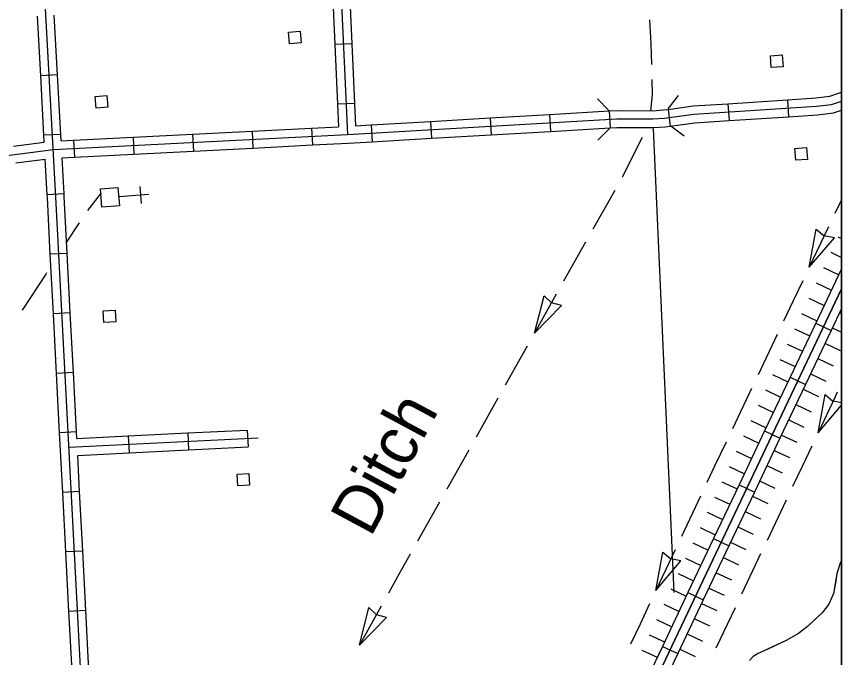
# Model space of a CAD drawing. Extents: x -0.3 to 2.65, y 0 to 1.9.
# Drawn here: x 0.9445 to 1.0319, y 0.2492 to 0.3171 of the extents above; entities that cross this region are included whole.
import ezdxf

# ---------------------------------------------------------------- set-up
doc = ezdxf.new("R2010")
doc.units = 0
for name, color, linetype in [('DSN_DRFT_DNC', 7, 'Continuous'), ('Level 12', 7, 'Continuous'), ('Level 15', 7, 'Continuous'), ('Level 19', 7, 'Continuous'), ('Level 20', 7, 'Continuous'), ('Level 29', 7, 'Continuous'), ('Level 32', 7, 'Continuous'), ('Level 33', 7, 'Continuous'), ('Level 36', 7, 'Continuous'), ('Level 37', 7, 'Continuous'), ('Level 6', 7, 'Continuous')]:
    doc.layers.add(name, color=color, linetype=linetype)

msp = doc.modelspace()

# ---------------------------------------------------------------- linework, layer by layer
at = {"layer": 'DSN_DRFT_DNC'}
msp.add_lwpolyline([(0.38477, 0.541667), (1.031896, 0.541667), (1.031896, 0.144296), (0.38477, 0.144296)], close=True, dxfattribs=at)
at = {"layer": 'Level 12'}
for p, q in [((1.031886, 0.297696), (1.031195, 0.296244)), ((1.028481, 0.290539), (1.029225, 0.294577)), ((1.029225, 0.294577), (1.030057, 0.293868)), ((1.031145, 0.293664), (1.03007, 0.293862)), ((1.028481, 0.290539), (1.031145, 0.293664)), ((0.99935, 0.283548), (1.000367, 0.287527)), ((1.000367, 0.287527), (1.001149, 0.286763)), ((0.99935, 0.283548), (1.00222, 0.286485)), ((1.00222, 0.286485), (1.001161, 0.286756)), ((1.029418, 0.273004), (1.030158, 0.277044)), ((1.030158, 0.277044), (1.030991, 0.276335)), ((1.031886, 0.276168), (1.031004, 0.276329)), ((1.029418, 0.273004), (1.031886, 0.275906)), ((1.012229, 0.25629), (1.012963, 0.260331)), ((1.012963, 0.260331), (1.013797, 0.259624)), ((1.012229, 0.25629), (1.014885, 0.259423)), ((1.014885, 0.259423), (1.01381, 0.259618)), ((0.980824, 0.250474), (0.981816, 0.254459)), ((0.981816, 0.254459), (0.982603, 0.2537)), ((0.983676, 0.253429), (0.982615, 0.253693)), ((0.980824, 0.250474), (0.983676, 0.253429))]:
    msp.add_line(p, q, dxfattribs=at)
for points in [[(1.011564, 0.316751), (1.011693, 0.314214), (1.011751, 0.312017)], [(1.011792, 0.310438), (1.011834, 0.30884), (1.011664, 0.307139)], [(1.010765, 0.304304), (1.010633, 0.304062), (1.008712, 0.300208), (1.008636, 0.300071)], [(0.95344, 0.298424), (0.951995, 0.296546)], [(1.007862, 0.298694), (1.00554, 0.294563)], [(0.951087, 0.295256), (0.949735, 0.293179)], [(1.030516, 0.294818), (1.028481, 0.290539)], [(1.004767, 0.293187), (1.002445, 0.289056)], [(0.94764, 0.28996), (0.94755, 0.289822), (0.945041, 0.285998)], [(1.027802, 0.289112), (1.026784, 0.286973)], [(1.001671, 0.287679), (0.99935, 0.283548)], [(1.026784, 0.286973), (1.025766, 0.284833)], [(1.025088, 0.283407), (1.023052, 0.279128)], [(0.998576, 0.282171), (0.996254, 0.27804)], [(1.022373, 0.277702), (1.020338, 0.273423)], [(1.031451, 0.277284), (1.031219, 0.276801), (1.029418, 0.273004)], [(0.99548, 0.276663), (0.993159, 0.272532)], [(1.019659, 0.271996), (1.018447, 0.26945), (1.018445, 0.269445), (1.017628, 0.267715)], [(0.992385, 0.271155), (0.990063, 0.267024)], [(1.028741, 0.271577), (1.027726, 0.269436)], [(1.027726, 0.269436), (1.02671, 0.267295)], [(1.016953, 0.266287), (1.014928, 0.262003)], [(1.026033, 0.265868), (1.024003, 0.261587)], [(0.989289, 0.265647), (0.986968, 0.261516)], [(1.014254, 0.260574), (1.012229, 0.25629)], [(0.986194, 0.260139), (0.985064, 0.258129), (0.983885, 0.256001)], [(1.023326, 0.26016), (1.021295, 0.255878)], [(0.98312, 0.254619), (0.980823, 0.250474)], [(1.011554, 0.254862), (1.010542, 0.25272)], [(1.020618, 0.254451), (1.018587, 0.25017)], [(1.010542, 0.25272), (1.00953, 0.250578)]]:
    msp.add_lwpolyline(points, dxfattribs=at)
at = {"layer": 'Level 15'}
for p, q in [((0.979991, 0.31422), (0.978198, 0.314138)), ((0.948812, 0.310937), (0.94702, 0.310838)), ((0.980278, 0.307908), (0.978485, 0.307827)), ((1.019861, 0.307881), (1.019978, 0.30609)), ((1.026166, 0.308293), (1.026283, 0.306502)), ((1.007271, 0.307108), (1.007376, 0.305316)), ((1.013514, 0.30728), (1.013755, 0.305501)), ((0.994657, 0.30637), (0.994761, 0.304578)), ((1.000964, 0.306739), (1.001069, 0.304947)), ((0.97574, 0.305292), (0.975831, 0.3035)), ((0.982042, 0.305632), (0.982147, 0.30384)), ((0.988349, 0.306001), (0.988454, 0.304209)), ((0.949157, 0.304628), (0.947365, 0.30453)), ((0.95681, 0.30433), (0.956901, 0.302537)), ((0.96312, 0.304651), (0.963211, 0.302858)), ((0.96943, 0.304971), (0.969521, 0.303179)), ((0.9505, 0.304009), (0.950591, 0.302216)), ((0.949503, 0.298319), (0.94771, 0.298221)), ((0.949832, 0.292007), (0.94804, 0.291914)), ((1.031886, 0.290341), (1.031874, 0.290316)), ((1.031874, 0.290316), (1.031886, 0.29031)), ((1.031886, 0.286153), (1.030787, 0.283838)), ((0.950161, 0.285698), (0.948369, 0.285604)), ((1.029166, 0.284607), (1.030787, 0.283838)), ((0.95049, 0.279388), (0.948698, 0.279295)), ((1.026458, 0.278899), (1.028079, 0.27813)), ((0.950819, 0.273079), (0.949027, 0.272985)), ((0.962609, 0.272972), (0.962698, 0.271179)), ((0.96892, 0.273285), (0.969009, 0.271492)), ((1.023749, 0.273191), (1.025371, 0.272421)), ((0.956299, 0.272658), (0.956388, 0.270866)), ((0.951148, 0.266769), (0.949356, 0.266676)), ((1.021041, 0.267482), (1.022663, 0.266713)), ((1.018333, 0.261774), (1.019955, 0.261005)), ((0.951477, 0.260459), (0.949685, 0.260366)), ((1.015625, 0.256066), (1.017247, 0.255296)), ((0.951806, 0.25415), (0.950013, 0.254056)), ((1.012917, 0.250357), (1.014539, 0.249588))]:
    msp.add_line(p, q, dxfattribs=at)
for points in [[(0.980914, 0.375083), (0.977798, 0.372691), (0.976942, 0.371974), (0.976392, 0.371185), (0.976158, 0.370335), (0.975971, 0.369189), (0.976279, 0.368153), (0.976461, 0.365336), (0.977251, 0.346933), (0.977728, 0.340622), (0.978318, 0.33161), (0.979546, 0.304604)], [(0.948639, 0.297983), (0.944541, 0.372833)], [(0.977911, 0.32045), (0.978198, 0.314138)], [(0.979704, 0.320532), (0.979991, 0.31422)], [(0.94702, 0.310838), (0.946674, 0.317147)], [(0.948812, 0.310937), (0.948466, 0.317245)], [(0.978198, 0.314138), (0.978485, 0.307827)], [(0.979991, 0.31422), (0.980278, 0.307908)], [(0.947365, 0.30453), (0.94702, 0.310838)], [(0.949157, 0.304628), (0.948812, 0.310937)], [(1.026166, 0.308293), (1.029168, 0.30849), (1.030651, 0.308672), (1.031697, 0.309012), (1.031886, 0.309096)], [(0.948349, 0.303017), (0.979546, 0.304604), (1.008074, 0.306273), (1.011914, 0.306257), (1.013131, 0.306339), (1.016253, 0.306762), (1.02925, 0.307613), (1.030842, 0.307808), (1.031886, 0.308147)], [(0.978485, 0.307827), (0.978594, 0.305437)], [(0.980278, 0.307908), (0.980386, 0.305535)], [(1.013514, 0.30728), (1.016165, 0.307639), (1.019861, 0.307881)], [(1.019861, 0.307881), (1.026166, 0.308293)], [(1.000964, 0.306739), (1.007271, 0.307108)], [(1.007271, 0.307108), (1.00805, 0.307154), (1.011886, 0.307138), (1.013042, 0.307216), (1.013514, 0.30728)], [(1.026283, 0.306502), (1.029336, 0.306702), (1.031041, 0.306912), (1.031886, 0.307186)], [(0.988349, 0.306001), (0.994657, 0.30637)], [(0.994657, 0.30637), (1.000964, 0.306739)], [(1.013755, 0.305501), (1.016344, 0.305852), (1.019978, 0.30609)], [(1.019978, 0.30609), (1.026283, 0.306502)], [(0.96943, 0.304971), (0.97574, 0.305292)], [(0.97574, 0.305292), (0.978594, 0.305437)], [(0.980386, 0.305535), (0.982042, 0.305632)], [(0.982042, 0.305632), (0.988349, 0.306001)], [(1.001069, 0.304947), (1.007376, 0.305316)], [(1.007376, 0.305316), (1.008099, 0.305358), (1.011943, 0.305343), (1.013223, 0.305429), (1.013755, 0.305501)], [(0.947406, 0.303786), (0.947365, 0.30453)], [(0.949195, 0.303942), (0.949157, 0.304628)], [(0.9505, 0.304009), (0.95681, 0.30433)], [(0.95681, 0.30433), (0.96312, 0.304651)], [(0.96312, 0.304651), (0.96943, 0.304971)], [(0.988454, 0.304209), (0.994761, 0.304578)], [(0.994761, 0.304578), (1.001069, 0.304947)], [(0.944151, 0.303377), (0.947406, 0.303786)], [(0.949195, 0.303942), (0.9505, 0.304009)], [(0.969521, 0.303179), (0.975831, 0.3035)], [(0.975831, 0.3035), (0.979596, 0.303691), (0.982147, 0.30384)], [(0.982147, 0.30384), (0.988454, 0.304209)], [(0.82448, 0.29532), (0.861174, 0.296964), (0.869268, 0.297214), (0.882271, 0.297741), (0.885311, 0.298019), (0.890649, 0.298892), (0.9031, 0.299971), (0.907709, 0.300247), (0.912716, 0.300468), (0.926784, 0.301246), (0.939403, 0.302056), (0.943185, 0.302368), (0.948349, 0.303017)], [(0.950591, 0.302216), (0.956901, 0.302537)], [(0.956901, 0.302537), (0.963211, 0.302858)], [(0.963211, 0.302858), (0.969521, 0.303179)], [(0.944375, 0.301596), (0.947504, 0.30199)], [(0.94771, 0.298221), (0.947504, 0.30199)], [(0.949293, 0.30215), (0.950591, 0.302216)], [(0.949503, 0.298319), (0.949293, 0.30215)], [(0.94804, 0.291914), (0.947726, 0.297934), (0.94771, 0.298221)], [(0.949832, 0.292007), (0.949518, 0.29803), (0.949503, 0.298319)], [(0.952994, 0.176198), (0.954135, 0.176338), (0.954452, 0.176453), (0.954691, 0.176672), (0.954797, 0.176907), (0.954759, 0.178156), (0.953909, 0.199316), (0.953966, 0.199969), (0.954188, 0.200668), (0.954642, 0.201513), (0.954847, 0.202103), (0.95484, 0.202415), (0.954669, 0.202682), (0.953465, 0.203597), (0.953164, 0.204036), (0.953059, 0.2048), (0.953132, 0.205394), (0.953481, 0.206991), (0.953507, 0.207774), (0.951694, 0.239369), (0.948639, 0.297983)], [(0.948369, 0.285604), (0.94804, 0.291914)], [(0.950161, 0.285698), (0.949832, 0.292007)], [(1.031874, 0.290316), (1.029166, 0.284607)], [(0.948698, 0.279295), (0.948369, 0.285604)], [(0.95049, 0.279388), (0.950161, 0.285698)], [(1.029166, 0.284607), (1.026458, 0.278899)], [(1.030787, 0.283838), (1.028079, 0.27813)], [(0.949027, 0.272985), (0.948698, 0.279295)], [(0.950819, 0.273079), (0.95049, 0.279388)], [(1.026458, 0.278899), (1.023749, 0.273191)], [(1.028079, 0.27813), (1.025371, 0.272421)], [(0.949356, 0.266676), (0.949027, 0.272985)], [(0.950855, 0.272388), (0.950819, 0.273079)], [(0.956299, 0.272658), (0.962609, 0.272972)], [(0.962609, 0.272972), (0.96892, 0.273285)], [(1.023749, 0.273191), (1.021041, 0.267482)], [(0.950032, 0.271465), (0.970086, 0.272461)], [(0.950855, 0.272388), (0.956299, 0.272658)], [(1.025371, 0.272421), (1.022663, 0.266713)], [(0.956388, 0.270866), (0.962698, 0.271179)], [(0.962698, 0.271179), (0.969009, 0.271492)], [(0.950949, 0.270595), (0.956388, 0.270866)], [(0.951148, 0.266769), (0.950949, 0.270595)], [(0.951477, 0.260459), (0.951148, 0.266769)], [(1.021041, 0.267482), (1.018333, 0.261774)], [(1.022663, 0.266713), (1.019955, 0.261005)], [(0.949685, 0.260366), (0.949356, 0.266676)], [(1.018333, 0.261774), (1.015625, 0.256066)], [(1.019955, 0.261005), (1.017247, 0.255296)], [(0.950013, 0.254056), (0.949685, 0.260366)], [(0.951806, 0.25415), (0.951477, 0.260459)], [(1.015625, 0.256066), (1.012917, 0.250357)], [(1.017247, 0.255296), (1.014539, 0.249588)], [(0.950342, 0.247747), (0.950013, 0.254056)], [(0.952135, 0.24784), (0.951806, 0.25415)], [(1.012917, 0.250357), (1.010209, 0.244649)], [(1.014539, 0.249588), (1.011831, 0.243879)]]:
    msp.add_lwpolyline(points, dxfattribs=at)
at = {"layer": 'Level 19'}
for points in [[(0.973379, 0.314235), (0.973283, 0.315477), (0.974528, 0.315573), (0.974625, 0.314331)], [(1.024454, 0.311701), (1.024358, 0.312943), (1.025604, 0.31304), (1.0257, 0.311798)], [(0.952889, 0.307404), (0.952792, 0.308646), (0.954038, 0.308743), (0.954134, 0.307501)], [(1.027053, 0.301883), (1.026957, 0.303125), (1.028202, 0.303221), (1.028298, 0.301979)], [(0.953725, 0.284692), (0.953651, 0.285935), (0.954898, 0.286009), (0.954972, 0.284766)], [(0.967904, 0.267361), (0.96783, 0.268604), (0.969077, 0.268678), (0.969151, 0.267435)]]:
    msp.add_lwpolyline(points, close=True, dxfattribs=at)
at = {"layer": 'Level 20'}
msp.add_lwpolyline([(1.011933, 0.305258), (1.014134, 0.256058)], dxfattribs=at)
at = {"layer": 'Level 29'}
for points in [[(1.013526, 0.307319), (1.014614, 0.308747)], [(1.00602, 0.308411), (1.007284, 0.307136)], [(1.007345, 0.305275), (1.006071, 0.304011)], [(1.015229, 0.30442), (1.013801, 0.305507)]]:
    msp.add_lwpolyline(points, dxfattribs=at)
at = {"layer": 'Level 32'}
for p, q in [((0.957535, 0.299093), (0.957674, 0.297303)), ((0.958499, 0.298267), (0.955287, 0.298018))]:
    msp.add_line(p, q, dxfattribs=at)
msp.add_lwpolyline([(0.95335, 0.298843), (0.955212, 0.298987), (0.955361, 0.297056), (0.9535, 0.296912)], close=True, dxfattribs=at)
at = {"layer": 'Level 33'}
msp.add_lwpolyline([(1.031886, 0.259416), (1.031785, 0.259274), (1.031412, 0.258085), (1.031269, 0.257053), (1.031046, 0.255969), (1.030538, 0.254833), (1.029837, 0.253913), (1.028964, 0.253079), (1.028294, 0.25245), (1.027356, 0.251708), (1.026045, 0.250981), (1.024145, 0.250086), (1.02306, 0.249589), (1.022539, 0.249281), (1.022144, 0.248873)], dxfattribs=at)
at = {"layer": 'Level 36'}
msp.add_lwpolyline([(1.031886, 0.259416), (1.031785, 0.259274), (1.031412, 0.258085), (1.031046, 0.255969), (1.030538, 0.254833), (1.029837, 0.253913), (1.028294, 0.25245), (1.027356, 0.251708), (1.026045, 0.250981), (1.02306, 0.249589), (1.022539, 0.249281), (1.022144, 0.248873)], dxfattribs=at)
at = {"layer": 'Level 37'}
for p, q in [((1.031518, 0.293754), (1.031886, 0.293579)), ((1.031518, 0.293754), (1.031886, 0.293579)), ((1.030749, 0.292132), (1.031886, 0.291592)), ((1.029979, 0.29051), (1.031601, 0.289741)), ((1.02921, 0.288888), (1.030832, 0.288119)), ((1.02921, 0.288888), (1.030832, 0.288119)), ((1.028441, 0.287267), (1.030062, 0.286497)), ((1.027671, 0.285645), (1.029293, 0.284876)), ((1.031684, 0.285728), (1.031886, 0.285632)), ((1.026902, 0.284023), (1.028524, 0.283254)), ((1.026902, 0.284023), (1.028524, 0.283254)), ((1.030915, 0.284106), (1.031886, 0.283646)), ((1.030145, 0.282485), (1.031767, 0.281715)), ((1.030145, 0.282485), (1.031767, 0.281715)), ((1.026133, 0.282402), (1.027754, 0.281632)), ((1.025363, 0.28078), (1.026985, 0.280011)), ((1.029376, 0.280863), (1.030998, 0.280094)), ((1.024594, 0.279158), (1.026216, 0.278389)), ((1.024594, 0.279158), (1.026216, 0.278389)), ((1.028607, 0.279241), (1.030228, 0.278472)), ((1.023825, 0.277537), (1.025446, 0.276767)), ((1.027837, 0.27762), (1.029459, 0.27685)), ((1.027837, 0.27762), (1.029459, 0.27685)), ((1.023055, 0.275915), (1.024677, 0.275146)), ((1.027068, 0.275998), (1.02869, 0.275229)), ((1.022286, 0.274293), (1.023908, 0.273524)), ((1.022286, 0.274293), (1.023908, 0.273524)), ((1.026299, 0.274376), (1.02792, 0.273607)), ((1.021517, 0.272672), (1.023138, 0.271902)), ((1.025529, 0.272755), (1.027151, 0.271985)), ((1.025529, 0.272755), (1.027151, 0.271985)), ((1.02476, 0.271133), (1.026382, 0.270364)), ((1.020747, 0.27105), (1.022369, 0.270281)), ((1.019978, 0.269428), (1.0216, 0.268659)), ((1.019978, 0.269428), (1.0216, 0.268659)), ((1.023991, 0.269511), (1.025612, 0.268742)), ((1.019209, 0.267807), (1.02083, 0.267037)), ((1.023221, 0.26789), (1.024843, 0.26712)), ((1.023221, 0.26789), (1.024843, 0.26712)), ((1.018439, 0.266185), (1.020061, 0.265416)), ((1.022452, 0.266268), (1.024074, 0.265499)), ((1.01767, 0.264563), (1.019292, 0.263794)), ((1.01767, 0.264563), (1.019292, 0.263794)), ((1.021683, 0.264646), (1.023304, 0.263877)), ((1.0169, 0.262942), (1.018522, 0.262172)), ((1.020913, 0.263024), (1.022535, 0.262255)), ((1.020913, 0.263024), (1.022535, 0.262255)), ((1.016131, 0.26132), (1.017753, 0.26055)), ((1.020144, 0.261403), (1.021766, 0.260633)), ((1.015362, 0.259698), (1.016983, 0.258929)), ((1.015362, 0.259698), (1.016983, 0.258929)), ((1.019374, 0.259781), (1.020996, 0.259012)), ((1.014592, 0.258076), (1.016214, 0.257307)), ((1.018605, 0.258159), (1.020227, 0.25739)), ((1.018605, 0.258159), (1.020227, 0.25739)), ((1.013823, 0.256455), (1.015445, 0.255685)), ((1.017836, 0.256538), (1.019457, 0.255768)), ((1.013054, 0.254833), (1.014675, 0.254064)), ((1.013054, 0.254833), (1.014675, 0.254064)), ((1.017066, 0.254916), (1.018688, 0.254147)), ((1.012284, 0.253211), (1.013906, 0.252442)), ((1.016297, 0.253294), (1.017919, 0.252525)), ((1.016297, 0.253294), (1.017919, 0.252525)), ((1.011515, 0.25159), (1.013137, 0.25082)), ((1.015528, 0.251673), (1.017149, 0.250903)), ((1.010746, 0.249968), (1.012367, 0.249199)), ((1.010746, 0.249968), (1.012367, 0.249199)), ((1.014758, 0.250051), (1.01638, 0.249282))]:
    msp.add_line(p, q, dxfattribs=at)
for points in [[(1.031886, 0.288247), (1.009606, 0.241284), (0.989269, 0.194855), (0.982693, 0.180605), (0.98227, 0.179654), (0.98176, 0.178541), (0.981303, 0.177756), (0.980534, 0.176579), (0.979422, 0.174925), (0.958834, 0.144274)], [(0.958834, 0.144274), (0.979422, 0.174925), (0.980534, 0.176579), (0.981303, 0.177756), (0.98176, 0.178541), (0.98227, 0.179654), (0.982693, 0.180605), (0.989269, 0.194855), (1.009606, 0.241284), (1.031886, 0.288247)]]:
    msp.add_lwpolyline(points, dxfattribs=at)
at = {"layer": 'Level 6'}
msp.add_line((1.031886, 0.144274), (1.031886, 0.541644), dxfattribs=at)

# ---------------------------------------------------------------- texts
at = {"layer": 'Level 12'}
msp.add_text('Ditch', height=0.0050545, rotation=61.79837, dxfattribs=at).set_placement((0.981979, 0.261809))

doc.saveas('drawing.dxf')
